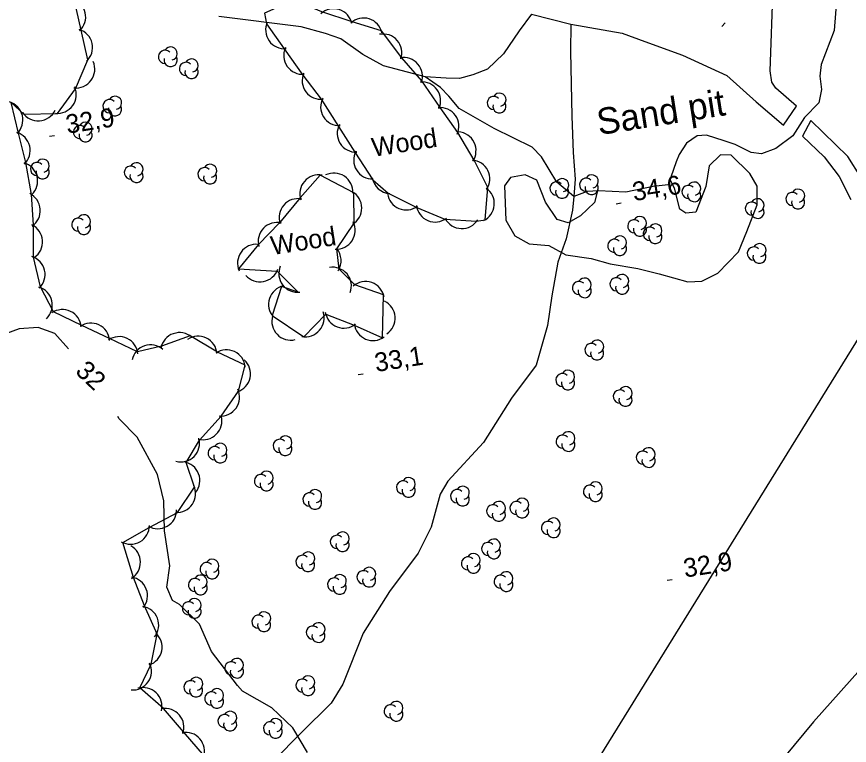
# Model space of a CAD drawing. Extents: x 646142 to 649934, y 5874075 to 5876351.
# Drawn here: x 648244.3 to 648377.1, y 5875740.3 to 5875856.5 of the extents above; entities that cross this region are included whole.
import ezdxf

# ---------------------------------------------------------------- set-up
doc = ezdxf.new("R2010")
doc.units = 0
for name, color, linetype in [('Niveau 2', 7, 'Continuous'), ('Niveau 21', 7, 'Continuous'), ('Niveau 22', 7, 'Continuous'), ('Niveau 3', 7, 'Continuous'), ('Niveau 36', 7, 'Continuous'), ('Niveau 44', 7, 'Continuous'), ('Niveau 54', 7, 'Continuous')]:
    doc.layers.add(name, color=color, linetype=linetype)

msp = doc.modelspace()

# ---------------------------------------------------------------- linework, layer by layer
at = {"layer": 'Niveau 2'}
for points in [[(648336.97, 5875828.7), (648336.48, 5875826.83), (648334.25, 5875824.71), (648332.28, 5875823.59), (648330.53, 5875824.14), (648328.67, 5875826.92), (648327.32, 5875830.42), (648325.44, 5875831.25), (648323.08, 5875830.84), (648322.15, 5875829.51), (648322.33, 5875824.03), (648323.78, 5875821.5), (648326.09, 5875820.25), (648329.19, 5875819.97), (648331.92, 5875818.52), (648335.95, 5875817.91), (648338.98, 5875817.06), (648343.42, 5875816.31), (648346.79, 5875815.48), (648351.39, 5875814.17), (648353.6, 5875814.29), (648356.18, 5875815.57), (648359.46, 5875818.97), (648360.81, 5875822.23), (648362.42, 5875826.47), (648362.43, 5875829.45), (648361.25, 5875831.48), (648358.3, 5875834.4), (648356.59, 5875834.44), (648354.78, 5875832.7), (648354.23, 5875829.39), (648352.66, 5875825.32), (648351.08, 5875825.14), (648350.12, 5875825.76), (648349.24, 5875829.13), (648348.53, 5875830.55)], [(648252.62, 5875803.49), (648250.43, 5875805.96), (648247.79, 5875806.9), (648244.72, 5875806.67), (648237.76, 5875804.12)], [(648290.71, 5875739.11), (648288.36, 5875743.06), (648285.03, 5875746.24), (648280.37, 5875748.92), (648279.56, 5875749.83), (648275.39, 5875755.25), (648273.52, 5875759.58), (648270.31, 5875762.72), (648269.18, 5875763.38), (648268.27, 5875765.49), (648268.76, 5875768.91), (648267.89, 5875774.47), (648267.81, 5875779.28), (648266.81, 5875783.45), (648263.56, 5875789.4), (648260.71, 5875792.34), (648260.47, 5875792.73)]]:
    msp.add_lwpolyline(points, dxfattribs=at)
at = {"layer": 'Niveau 21'}
for points in [[(648326.42, 5875856.87), (648332.7, 5875855.29), (648340.91, 5875853.85), (648344.54, 5875852.52), (648350.52, 5875850.35), (648357.6, 5875847.1), (648362.25, 5875842.87), (648366.63, 5875839.2), (648368.68, 5875842.22), (648365.39, 5875845.06), (648364.75, 5875846.05), (648364.5, 5875847.86), (648364.63, 5875850.74), (648364.86, 5875858.32)], [(648378.94, 5875830.89), (648376.87, 5875834.17), (648370.97, 5875839.91), (648369.68, 5875837.4), (648373.11, 5875834.11), (648375.51, 5875830.98), (648377.38, 5875827.34)], [(648380.26, 5875753.88), (648371.43, 5875744.03), (648363.69, 5875734.72)]]:
    msp.add_lwpolyline(points, dxfattribs=at)
at = {"layer": 'Niveau 22'}
for points in [[(648326.42, 5875856.87), (648324.46, 5875854.2), (648321.99, 5875850.57), (648319.44, 5875848.08), (648317.11, 5875847.22), (648314.98, 5875846.6), (648312.81, 5875846.66), (648309.49, 5875846.86), (648302.85, 5875848.65), (648299.52, 5875850.46), (648296.03, 5875852.94), (648293.57, 5875853.79), (648289.72, 5875854.87), (648276.58, 5875856.5)], [(648332.7, 5875855.29), (648332.69, 5875850.93), (648332.89, 5875840.63), (648333.1, 5875834.8), (648333.41, 5875830.58), (648333.17, 5875827.78), (648332.99, 5875825.62), (648331.96, 5875821.07), (648330.65, 5875817.31), (648329.68, 5875811.96), (648329.01, 5875807.21), (648327.2, 5875800.89), (648323.26, 5875795.65), (648318.78, 5875788.55), (648313.08, 5875782.38), (648311.86, 5875780.33), (648310.43, 5875775.07), (648308.35, 5875770.89), (648303.79, 5875764.81), (648299.6, 5875758.18), (648296.34, 5875750.01), (648294.51, 5875747), (648289.72, 5875742.27), (648281.02, 5875733.45)]]:
    msp.add_lwpolyline(points, dxfattribs=at)
at = {"layer": 'Niveau 3'}
for p, q in [((648356.79, 5875854.91), (648357.31, 5875855.52)), ((648249.57, 5875837.4), (648250.36, 5875837.52)), ((648339.93, 5875826.65), (648340.72, 5875826.77)), ((648298.81, 5875799.4), (648299.6, 5875799.52)), ((648348.07, 5875766.6), (648348.86, 5875766.72))]:
    msp.add_line(p, q, dxfattribs=at)
at = {"layer": 'Niveau 36'}
msp.add_lwpolyline([(648600.59, 5876162.13), (648551.33, 5876082.95), (648424.31, 5875879.18), (648303.24, 5875683.36), (648187.06, 5875496.14), (648107.92, 5875369.28), (648085.7, 5875326.63)], dxfattribs=at)
at = {"layer": 'Niveau 44'}
for points in [[(648274.3, 5875738.54), (648270.94, 5875742.44), (648267.77, 5875746.12), (648263.98, 5875749.43), (648265.78, 5875753.21), (648266.74, 5875757.97), (648264.73, 5875762.49), (648262.98, 5875767.02), (648261.28, 5875772.6), (648265.49, 5875775.01), (648269.98, 5875777.41), (648272.7, 5875781.43), (648271.35, 5875785.39), (648273.48, 5875788.94), (648276.95, 5875792.78), (648279.73, 5875796.77), (648280.76, 5875800.9), (648276.38, 5875802.99), (648272.02, 5875805.56), (648267.44, 5875803.95), (648263.63, 5875803), (648259.12, 5875805.15), (648254.73, 5875807.24), (648250.22, 5875809.4), (648248.16, 5875813.39), (648247.05, 5875818.12), (648247.04, 5875823.27), (648246.69, 5875828.11), (648245.79, 5875833.2), (648244.65, 5875837.92), (648243.48, 5875842.78), (648245.47, 5875840.93), (648250.84, 5875841.06), (648253.7, 5875844.98), (648255.7, 5875849.58), (648254.63, 5875854.31), (648253.5, 5875859.33)], [(648284.2, 5875855.33), (648287, 5875851.37), (648290, 5875847.17), (648292.92, 5875843.3), (648295.68, 5875838.98), (648298.26, 5875834.87), (648301.12, 5875830.46), (648303.58, 5875828.31), (648308.16, 5875826.04), (648312.64, 5875824.17), (648317.7, 5875823.84), (648319.08, 5875824.1), (648319.46, 5875829.22), (648317.32, 5875833.57), (648314.7, 5875838.03), (648311.89, 5875841.99), (648308.98, 5875846.27), (648305.79, 5875849.93), (648302.51, 5875854.22), (648297.87, 5875855.66), (648293.01, 5875857.24), (648288.55, 5875859.16), (648283.88, 5875857.02), (648284.2, 5875855.33)], [(648286.57, 5875813.46), (648285.09, 5875808.83), (648290.12, 5875805.44), (648293.62, 5875809.04), (648298.14, 5875807.27), (648302.7, 5875805.24), (648302.85, 5875812.1), (648298.26, 5875813.69), (648295.77, 5875816.21), (648295.41, 5875819.46), (648298.16, 5875823.54), (648298.12, 5875828.4), (648292.74, 5875831.22), (648289.56, 5875827.56), (648286.27, 5875823.62), (648282.89, 5875820.13), (648279.71, 5875816.25), (648285.86, 5875815.91), (648289.21, 5875812.53), (648286.57, 5875813.46)]]:
    msp.add_lwpolyline(points, dxfattribs=at)
for centre, radius, start, end in [((648252.35, 5875856.43), 3, 312.7076, 72.6856), ((648294.89, 5875854.74), 3, 12.762, 132.74), ((648299.67, 5875853.26), 3, 12.762, 132.74), ((648287.04, 5875854.37), 3, 155.326, 275.3039), ((648253.44, 5875851.56), 3, 312.7076, 72.6856), ((648302.77, 5875850.72), 3, 341.0778, 101.0557), ((648268, 5875850.08), 1.05, 44.1154, 269.804), ((648268.9, 5875850.61), 1.05, 282.2692, 149.7263), ((648289.93, 5875850.29), 3, 155.326, 275.3039), ((648268.9, 5875849.56), 1.05, 166.9369, 29.6212), ((648272.23, 5875848.69), 1.05, 282.2692, 149.7263), ((648306.06, 5875846.95), 3, 341.0778, 101.0557), ((648253.8, 5875848.1), 3, 263.8632, 23.8411), ((648271.33, 5875848.16), 1.05, 44.1154, 269.804), ((648272.23, 5875847.64), 1.05, 166.9369, 29.6212), ((648292.87, 5875846.3), 3, 157.0157, 276.9937), ((648308.96, 5875843.07), 3, 335.3427, 95.3206), ((648250.85, 5875844.06), 3, 263.8632, 23.8411), ((648259.13, 5875842.21), 1.05, 44.1154, 269.804), ((648260.03, 5875842.74), 1.05, 282.2692, 149.7263), ((648295.81, 5875842.1), 3, 152.1177, 272.0956), ((648320.43, 5875842.71), 1.05, 44.1154, 269.804), ((648321.33, 5875843.24), 1.05, 282.2692, 149.7263), ((648242.33, 5875840), 3, 313.5918, 73.5697), ((648260.03, 5875841.69), 1.05, 166.9369, 29.6212), ((648311.86, 5875838.99), 3, 335.3427, 95.3206), ((648321.33, 5875842.19), 1.05, 166.9369, 29.6212), ((648247.77, 5875842.86), 3, 214.0355, 334.0135), ((648254.43, 5875838.07), 1.05, 44.1154, 269.804), ((648255.33, 5875838.6), 1.05, 282.2692, 149.7263), ((648298.46, 5875837.87), 3, 152.1177, 272.0956), ((648243.5, 5875835.14), 3, 313.5918, 73.5697), ((648255.33, 5875837.55), 1.05, 166.9369, 29.6212), ((648314.6, 5875835.1), 3, 326.1861, 86.1641), ((648301.09, 5875833.59), 3, 151.2927, 271.2706), ((648248.49, 5875832.71), 1.05, 282.2692, 149.7263), ((648244.68, 5875830.28), 3, 313.5918, 73.5697), ((648247.59, 5875832.18), 1.05, 44.1154, 269.804), ((648262.55, 5875831.61), 1.05, 44.1154, 269.804), ((648263.45, 5875832.14), 1.05, 282.2692, 149.7263), ((648274.29, 5875831.36), 1.05, 44.1154, 269.804), ((648275.19, 5875831.89), 1.05, 282.2692, 149.7263), ((648316.81, 5875830.61), 3, 326.1861, 86.1641), ((648248.49, 5875831.66), 1.05, 166.9369, 29.6212), ((648263.45, 5875831.09), 1.05, 166.9369, 29.6212), ((648275.19, 5875830.84), 1.05, 166.9369, 29.6212), ((648292.49, 5875828.24), 3, 79.0448, 199.0227), ((648294.94, 5875828.54), 3, 356.1929, 116.1709), ((648336.05, 5875830.2), 1.05, 282.2692, 149.7263), ((648304, 5875831.28), 3, 189.8685, 267.2165), ((648330.43, 5875829.08), 1.05, 44.1154, 269.804), ((648331.33, 5875829.61), 1.05, 282.2692, 149.7263), ((648335.15, 5875829.67), 1.05, 44.1154, 269.804), ((648352.39, 5875829.06), 1.05, 282.2692, 149.7263), ((648296.38, 5875825.96), 3, 300.4042, 60.3821), ((648317.52, 5875826.66), 3, 295.1927, 55.1706), ((648331.33, 5875828.56), 1.05, 166.9369, 29.6212), ((648336.05, 5875829.15), 1.05, 166.9369, 29.6212), ((648351.49, 5875828.53), 1.05, 44.1154, 269.804), ((648352.39, 5875828.01), 1.05, 166.9369, 29.6212), ((648368.06, 5875827.4), 1.05, 44.1154, 269.804), ((648368.96, 5875827.93), 1.05, 282.2692, 149.7263), ((648245.11, 5875825.56), 3, 304.1436, 64.1216), ((648289.21, 5875824.46), 3, 79.0448, 199.0227), ((648306.46, 5875828.65), 3, 187.3803, 307.3583), ((648362.49, 5875826.4), 1.05, 282.2692, 149.7263), ((648368.96, 5875826.88), 1.05, 166.9369, 29.6212), ((648311.08, 5875826.73), 3, 187.3803, 307.3583), ((648361.59, 5875825.87), 1.05, 44.1154, 269.804), ((648362.49, 5875825.35), 1.05, 166.9369, 29.6212), ((648255.07, 5875823.84), 1.05, 282.2692, 149.7263), ((648343.73, 5875823.57), 1.05, 282.2692, 149.7263), ((648245.47, 5875820.57), 3, 304.1436, 64.1216), ((648254.17, 5875823.31), 1.05, 44.1154, 269.804), ((648255.07, 5875822.79), 1.05, 166.9369, 29.6212), ((648285.85, 5875820.65), 3, 75.9171, 195.895), ((648295.33, 5875822.4), 3, 266.601, 26.5789), ((648315.33, 5875825.68), 3, 208.0359, 328.0139), ((648342.83, 5875823.04), 1.05, 44.1154, 269.804), ((648346.2, 5875822.38), 1.05, 282.2692, 149.7263), ((648343.73, 5875822.52), 1.05, 166.9369, 29.6212), ((648345.3, 5875821.85), 1.05, 44.1154, 269.804), ((648346.2, 5875821.33), 1.05, 166.9369, 29.6212), ((648339.65, 5875819.94), 1.05, 44.1154, 269.804), ((648340.55, 5875820.47), 1.05, 282.2692, 149.7263), ((648282.56, 5875817.18), 3, 84.2424, 204.2203), ((648293.09, 5875817.56), 3, 327.3902, 40.9226), ((648340.55, 5875819.42), 1.05, 166.9369, 29.6212), ((648361.9, 5875818.71), 1.05, 44.1154, 269.804), ((648362.8, 5875819.24), 1.05, 282.2692, 149.7263), ((648245.88, 5875815.35), 3, 313.1939, 73.1718), ((648362.8, 5875818.19), 1.05, 166.9369, 29.6212), ((648289.15, 5875815.53), 3, 157.2031, 277.1811), ((648294.72, 5875813.52), 3, 339.76, 99.7379), ((648283.15, 5875817.18), 3, 220.7783, 340.7562), ((648340.9, 5875814.33), 1.05, 282.2692, 149.7263), ((648299.98, 5875811.23), 3, 10.9162, 130.8942), ((648334.02, 5875813.22), 1.05, 44.1154, 269.804), ((648334.92, 5875813.75), 1.05, 282.2692, 149.7263), ((648340, 5875813.8), 1.05, 44.1154, 269.804), ((648340.9, 5875813.28), 1.05, 166.9369, 29.6212), ((648247.02, 5875810.48), 3, 313.1939, 73.1718), ((648287.51, 5875810.6), 3, 102.1681, 222.1461), ((648334.92, 5875812.7), 1.05, 166.9369, 29.6212), ((648301.7, 5875808.39), 3, 304.3113, 64.2892), ((648251.65, 5875806.76), 3, 4.5075, 124.4854), ((648288.04, 5875807.89), 3, 163.7025, 283.6805), ((648290.37, 5875808.43), 3, 259.3248, 19.3028), ((648296.53, 5875809.8), 3, 188.5848, 308.5627), ((648256.17, 5875804.61), 3, 4.5075, 124.4854), ((648301.18, 5875807.82), 3, 186.5869, 306.5648), ((648270.31, 5875803.09), 3, 49.3355, 169.3135), ((648260.68, 5875802.45), 3, 4.5075, 124.4854), ((648273.3, 5875802.51), 3, 4.4614, 124.4393), ((648336.91, 5875803.85), 1.05, 282.2692, 149.7263), ((648265.69, 5875801.15), 3, 48.7707, 168.7487), ((648277.81, 5875800.35), 3, 4.4614, 124.4393), ((648336.01, 5875803.32), 1.05, 44.1154, 269.804), ((648336.91, 5875802.8), 1.05, 166.9369, 29.6212), ((648278.63, 5875799.51), 3, 287.8398, 47.8178), ((648331.37, 5875798.52), 1.05, 44.1154, 269.804), ((648332.27, 5875799.05), 1.05, 282.2692, 149.7263), ((648332.27, 5875798), 1.05, 166.9369, 29.6212), ((648276.89, 5875795.78), 3, 265.146, 25.124), ((648340.54, 5875795.9), 1.05, 44.1154, 269.804), ((648341.44, 5875796.43), 1.05, 282.2692, 149.7263), ((648341.44, 5875795.38), 1.05, 166.9369, 29.6212), ((648274.06, 5875792), 3, 255.0213, 14.9993), ((648332.32, 5875789.24), 1.05, 282.2692, 149.7263), ((648270.52, 5875788.47), 3, 255.0213, 14.9993), ((648286.29, 5875788.03), 1.05, 44.1154, 269.804), ((648287.19, 5875788.56), 1.05, 282.2692, 149.7263), ((648331.42, 5875788.71), 1.05, 44.1154, 269.804), ((648332.32, 5875788.19), 1.05, 166.9369, 29.6212), ((648275.92, 5875786.87), 1.05, 44.1154, 269.804), ((648276.82, 5875787.4), 1.05, 282.2692, 149.7263), ((648287.19, 5875787.51), 1.05, 166.9369, 29.6212), ((648344.21, 5875786.16), 1.05, 44.1154, 269.804), ((648345.11, 5875786.69), 1.05, 282.2692, 149.7263), ((648276.82, 5875786.35), 1.05, 166.9369, 29.6212), ((648345.11, 5875785.64), 1.05, 166.9369, 29.6212), ((648270.55, 5875782.5), 3, 320.6958, 80.6737), ((648283.3, 5875782.42), 1.05, 44.1154, 269.804), ((648284.2, 5875782.95), 1.05, 282.2692, 149.7263), ((648284.2, 5875781.9), 1.05, 166.9369, 29.6212), ((648305.96, 5875781.4), 1.05, 44.1154, 269.804), ((648306.86, 5875781.93), 1.05, 282.2692, 149.7263), ((648336.67, 5875781.25), 1.05, 282.2692, 149.7263), ((648269.88, 5875780.4), 3, 265.9131, 25.891), ((648291.93, 5875780.01), 1.05, 282.2692, 149.7263), ((648306.86, 5875780.88), 1.05, 166.9369, 29.6212), ((648314.58, 5875780.01), 1.05, 44.1154, 269.804), ((648315.48, 5875780.54), 1.05, 282.2692, 149.7263), ((648335.77, 5875780.72), 1.05, 44.1154, 269.804), ((648336.67, 5875780.2), 1.05, 166.9369, 29.6212), ((648291.03, 5875779.48), 1.05, 44.1154, 269.804), ((648291.93, 5875778.96), 1.05, 166.9369, 29.6212), ((648315.48, 5875779.49), 1.05, 166.9369, 29.6212), ((648324.96, 5875778.64), 1.05, 282.2692, 149.7263), ((648320.34, 5875777.59), 1.05, 44.1154, 269.804), ((648321.24, 5875778.12), 1.05, 282.2692, 149.7263), ((648324.06, 5875778.11), 1.05, 44.1154, 269.804), ((648324.96, 5875777.59), 1.05, 166.9369, 29.6212), ((648266.85, 5875777.82), 3, 239.7662, 359.7442), ((648321.24, 5875777.07), 1.05, 166.9369, 29.6212), ((648262.51, 5875775.34), 3, 239.7662, 359.7442), ((648329.07, 5875774.95), 1.05, 44.1154, 269.804), ((648329.97, 5875775.48), 1.05, 282.2692, 149.7263), ((648296.31, 5875773.25), 1.05, 282.2692, 149.7263), ((648329.97, 5875774.43), 1.05, 166.9369, 29.6212), ((648295.41, 5875772.72), 1.05, 44.1154, 269.804), ((648296.31, 5875772.2), 1.05, 166.9369, 29.6212), ((648319.54, 5875771.59), 1.05, 44.1154, 269.804), ((648320.44, 5875772.12), 1.05, 282.2692, 149.7263), ((648261.08, 5875769.45), 3, 301.1671, 61.145), ((648320.44, 5875771.07), 1.05, 166.9369, 29.6212), ((648275.54, 5875768.91), 1.05, 282.2692, 149.7263), ((648289.92, 5875769.53), 1.05, 44.1154, 269.804), ((648290.82, 5875770.06), 1.05, 282.2692, 149.7263), ((648316.31, 5875769.28), 1.05, 44.1154, 269.804), ((648317.21, 5875769.81), 1.05, 282.2692, 149.7263), ((648274.64, 5875768.38), 1.05, 44.1154, 269.804), ((648290.82, 5875769.01), 1.05, 166.9369, 29.6212), ((648300.55, 5875767.61), 1.05, 282.2692, 149.7263), ((648317.21, 5875768.76), 1.05, 166.9369, 29.6212), ((648273.68, 5875766.37), 1.05, 282.2692, 149.7263), ((648275.54, 5875767.86), 1.05, 166.9369, 29.6212), ((648295.86, 5875766.45), 1.05, 282.2692, 149.7263), ((648299.65, 5875767.08), 1.05, 44.1154, 269.804), ((648321.53, 5875766.38), 1.05, 44.1154, 269.804), ((648322.43, 5875766.91), 1.05, 282.2692, 149.7263), ((648262.21, 5875764.12), 3, 321.0589, 81.0368), ((648272.78, 5875765.84), 1.05, 44.1154, 269.804), ((648294.96, 5875765.92), 1.05, 44.1154, 269.804), ((648300.55, 5875766.56), 1.05, 166.9369, 29.6212), ((648322.43, 5875765.86), 1.05, 166.9369, 29.6212), ((648273.68, 5875765.32), 1.05, 166.9369, 29.6212), ((648295.86, 5875765.4), 1.05, 166.9369, 29.6212), ((648272.71, 5875762.64), 1.05, 282.2692, 149.7263), ((648264, 5875759.45), 3, 321.0589, 81.0368), ((648271.81, 5875762.11), 1.05, 44.1154, 269.804), ((648272.71, 5875761.59), 1.05, 166.9369, 29.6212), ((648282.9, 5875759.98), 1.05, 44.1154, 269.804), ((648283.8, 5875760.51), 1.05, 282.2692, 149.7263), ((648283.8, 5875759.46), 1.05, 166.9369, 29.6212), ((648292.47, 5875758.78), 1.05, 282.2692, 149.7263), ((648264.53, 5875755.93), 3, 288.6574, 48.6354), ((648291.57, 5875758.25), 1.05, 44.1154, 269.804), ((648292.47, 5875757.73), 1.05, 166.9369, 29.6212), ((648279.46, 5875753.09), 1.05, 282.2692, 149.7263), ((648262.83, 5875752.09), 3, 265.4588, 25.4368), ((648278.56, 5875752.56), 1.05, 44.1154, 269.804), ((648279.46, 5875752.04), 1.05, 166.9369, 29.6212), ((648290.83, 5875750.31), 1.05, 282.2692, 149.7263), ((648272.06, 5875749.54), 1.05, 44.1154, 269.804), ((648272.96, 5875750.07), 1.05, 282.2692, 149.7263), ((648289.93, 5875749.78), 1.05, 44.1154, 269.804), ((648264.51, 5875746.48), 3, 346.2667, 106.2447), ((648272.96, 5875749.02), 1.05, 166.9369, 29.6212), ((648275.39, 5875747.74), 1.05, 44.1154, 269.804), ((648276.29, 5875748.27), 1.05, 282.2692, 149.7263), ((648290.83, 5875749.26), 1.05, 166.9369, 29.6212), ((648276.29, 5875747.22), 1.05, 166.9369, 29.6212), ((648268.02, 5875743.13), 3, 340.7534, 100.7314), ((648303.99, 5875745.7), 1.05, 44.1154, 269.804), ((648304.89, 5875746.23), 1.05, 282.2692, 149.7263), ((648277.49, 5875744.13), 1.05, 44.1154, 269.804), ((648278.39, 5875744.66), 1.05, 282.2692, 149.7263), ((648304.89, 5875745.18), 1.05, 166.9369, 29.6212), ((648278.39, 5875743.61), 1.05, 166.9369, 29.6212), ((648284.75, 5875742.97), 1.05, 44.1154, 269.804), ((648285.65, 5875743.5), 1.05, 282.2692, 149.7263), ((648271.28, 5875739.34), 3, 340.7534, 100.7314), ((648285.65, 5875742.45), 1.05, 166.9369, 29.6212)]:
    msp.add_arc(centre, radius, start, end, dxfattribs=at)
at = {"layer": 'Niveau 54'}
msp.add_lwpolyline([(648375.06, 5875858.99), (648374.73, 5875854.27), (648372.63, 5875848.84), (648372.43, 5875846.99), (648372.7, 5875844.84), (648372.29, 5875842.74), (648369.96, 5875840.39), (648368.13, 5875837.5), (648365.43, 5875835.46), (648363.11, 5875834.6), (648361.5, 5875834.82), (648358.9, 5875836.11), (648357.15, 5875836.66), (648354.34, 5875837.59), (648352.87, 5875837.48), (648351.14, 5875836.31), (648350.02, 5875834.51), (648349.54, 5875833.33), (648348.22, 5875829.68), (648345.85, 5875829.38), (648341.47, 5875828.47), (648337.13, 5875828.71), (648335.31, 5875828.57), (648333.17, 5875827.78), (648330.49, 5875830.1), (648328.02, 5875834.15), (648326.54, 5875835.64), (648320.5, 5875838.62), (648314.9, 5875841.85), (648313.27, 5875843.79), (648311.91, 5875845.18), (648309.49, 5875846.86)], dxfattribs=at)

# ---------------------------------------------------------------- texts
at = {"layer": 'Niveau 2'}
msp.add_text('32', height=3, rotation=316.2803, dxfattribs=at).set_placement((648253.54, 5875799.75))
at = {"layer": 'Niveau 3'}
for s, p in [('32,9 ', (648252.42, 5875837.8)), ('34,6 ', (648342.78, 5875827.06)), ('33,1 ', (648301.66, 5875799.8)), ('32,9 ', (648350.92, 5875767.01))]:
    msp.add_text(s, height=3, rotation=8.9405, dxfattribs=at).set_placement(p)
at = {"layer": 'Niveau 44'}
for p in [(648301.22, 5875834.12), (648285.11, 5875818.45)]:
    msp.add_text('Wood', height=3, rotation=8.9405, dxfattribs=at).set_placement(p)
at = {"layer": 'Niveau 54'}
msp.add_text('Sand pit', height=4.2, rotation=8.9405, dxfattribs=at).set_placement((648337.21, 5875837.58))

doc.saveas('drawing.dxf')
